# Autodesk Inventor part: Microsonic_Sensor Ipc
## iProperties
Shininess: 20.0
Length Units: 11269
Angle Units: 11279
Time Units: 11290
Mass Units: 11283
Length Display Precision: 2
Angle Display Precision: 2
Part Number: Microsonic_Sensor Ipc
Material: Nichtrostender Stahl - 440C
Document SubType Name: Modellieren
Description: Ipc-25 /CXX/M18
Checked By: Alves
Created: 2005-08
Designer: Ohle
Manufacturer: Standard
Standards Organization: Custom
Density: 0.0
Volumn: 0.0
Area: 0.0
PropertySet Name: Model Information
Control State: 0
Master: False
Checked Out: False
Last Check In By: Tanck
Last Check In Date: 2005-08-09
BESTELLNUMMER: Ipc-25 /CXX/M18
ME: ST
Title: Ipc Sensoren
Author: Ohle
Comments: keine Bemerkung
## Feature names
1. Grundkörper wms-25 [Revolution]
2. Pole [Extrusion]
3. Rundung Pole [Fillet]
4. Verdrehsicherung [Extrusion]
5. LED [Revolution]
